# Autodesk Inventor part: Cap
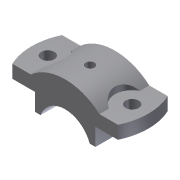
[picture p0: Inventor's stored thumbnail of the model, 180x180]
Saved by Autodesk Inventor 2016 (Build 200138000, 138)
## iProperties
Created: 2009-04
Part Number: Cap
Document SubType Name: Modeling
Designer: Sham
Density: 1 g/cm^3
Material: Generic
Mass: 94.0132 g
Surface Area: 184.419 cm^2
Volume: 94.0132 cm^3
Appearance: Default
Author: Sham
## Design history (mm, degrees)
sketch "Sketch1"
  geometry: L1 (-48.857, 23)-(48.857, 23); L2 (48.857, -23)-(-48.857, -23); A1 r 54 centre (0, 0) between (-48.857, 23) and (-48.857, -23); A2 r 54 centre (0, 0) between (48.857, -23) and (48.857, 23); 1 further point
  constraints: 4 end point, 4 point on circle, 2 centre point, 2 coincident, 1 horizontal, 1 parallel, 1 other
  dimensions: "d3" = 54 radius of A1; "d4" = 54 radius of A2; "d5" = 46 distance between parallel lines of L2 L1; "d6" = 23 distance from line of point (0, 0) L1
extrude "Extrusion1" new body sketch "Sketch1" distance "d7" = 12; taper "d8" = 0 deg
sketch "Sketch3"
  geometry: L1 (20.906, 0)-(20.906, -16); L2 (76.906, -0.137)-(76.906, -16.137); L3 (20.906, -16)-(26.23, -16); L4 (71.532, -16.137)-(76.906, -16.137); L5 (76.906, -0.137)-(76.857, 12); L6 (97.714, 0)-(0, 0) reference; L7 (76.857, 12)-(80.606, 12); L8 (17.108, 12)-(20.906, 12); L9 (20.906, 12)-(20.906, 0); L10 (0, 12)-(97.714, 12) reference; A1 r 24 centre (48.857, -24) between (71.532, -16.137) and (26.23, -16); A2 r 48 centre (48.857, -24) between (80.606, 12) and (17.108, 12); 3 further points
  constraints: 16 end point, 4 point on circle, 3 parallel, 3 perpendicular, 2 centre point, 2 coincident, 2 vertical alignment, 1 collinear, 1 midpoint, 1 vertical, 2 other
  dimensions: "d17" = 48 diameter of A1; "d18" = 16 distance of L1.start L1.end; "d19" = 56 distance between parallel lines of L2 L1; "d21" = 8 vertical distance of A1.centre L1.end; "d22" = 48 radius of A2; "d23" = 0 distance from line of L6 L1.start; "d38" = 31.74902 distance of L7.end point (48.857, 12); "d39" = 28 distance from line of point (48.857, 12) L5
extrude "Extrusion2" join sketch "Sketch3" stored distance "d24" = 12; taper "d25" = 0 deg
sketch "Sketch4"
  geometry: 2 further points
  dimensions: "d26" = 78 distance of point (39, 0) point (-39, 0)
hole "Hole1" sketch "Sketch4" at (-39, 0), (39, 0) diameter "d28" = 12; stored, may be unused: countersink angle "d32" = 90 deg, drill point angle "d34" = 118 deg; dims "d29" = 6, "d30" = 4, "d31" = 2, "d33" = 8
sketch "Sketch5"
  geometry: L1 (-31.749, -23)-(-31.749, 23) reference; L2 (-31.749, 14.263)-(-31.749, -14.263); C1 r 6 at (-39, 0) reference; A1 r 16 centre (-39, 0) between (-31.749, -14.263) and (-31.749, 14.263)
  constraints: 2 end point, 2 point on circle, 1 centre point, 1 coincident, 1 collinear, 1 point on line
  dimensions: "d35" = 16 radius of A1
extrude "Extrusion3" cut sketch "Sketch5" distance "d36" = 12; taper "d37" = 0 deg
mirror "Mirror2"
workplane "Work Plane4"
sketch "Sketch6"
  geometry: L1 (-31.749, 0)-(31.749, 0) reference; 1 further point
  dimensions: "d40" = 23 distance from line of L1 point (0, 23)
hole "Hole2" sketch "Sketch6" at (0, 23) diameter "d41" = 6; stored, may be unused: countersink angle "d45" = 90 deg, drill point angle "d47" = 118 deg; dims "d42" = 6, "d43" = 8, "d44" = 16, "d46" = 8
body "Solid1"
